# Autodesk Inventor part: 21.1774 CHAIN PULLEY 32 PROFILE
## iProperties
Company: MiniTec Framing Systems, LLC
Created: 2007-05
Part Number: 21.1774 CHAIN PULLEY 32 PROFILE
Material: Aluminum-6061
Document SubType Name: Modeling
Designer: Andy Moles
Density: 2.71 g/cm^3
Mass: 314.23 g
Surface Area: 764.397 cm^2
Volume: 115.952 cm^3
Author: Andy Moles
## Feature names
1. Extrusion1
2. Extrusion2
3. Hole1
4. Mirror1
5. Extrusion3
